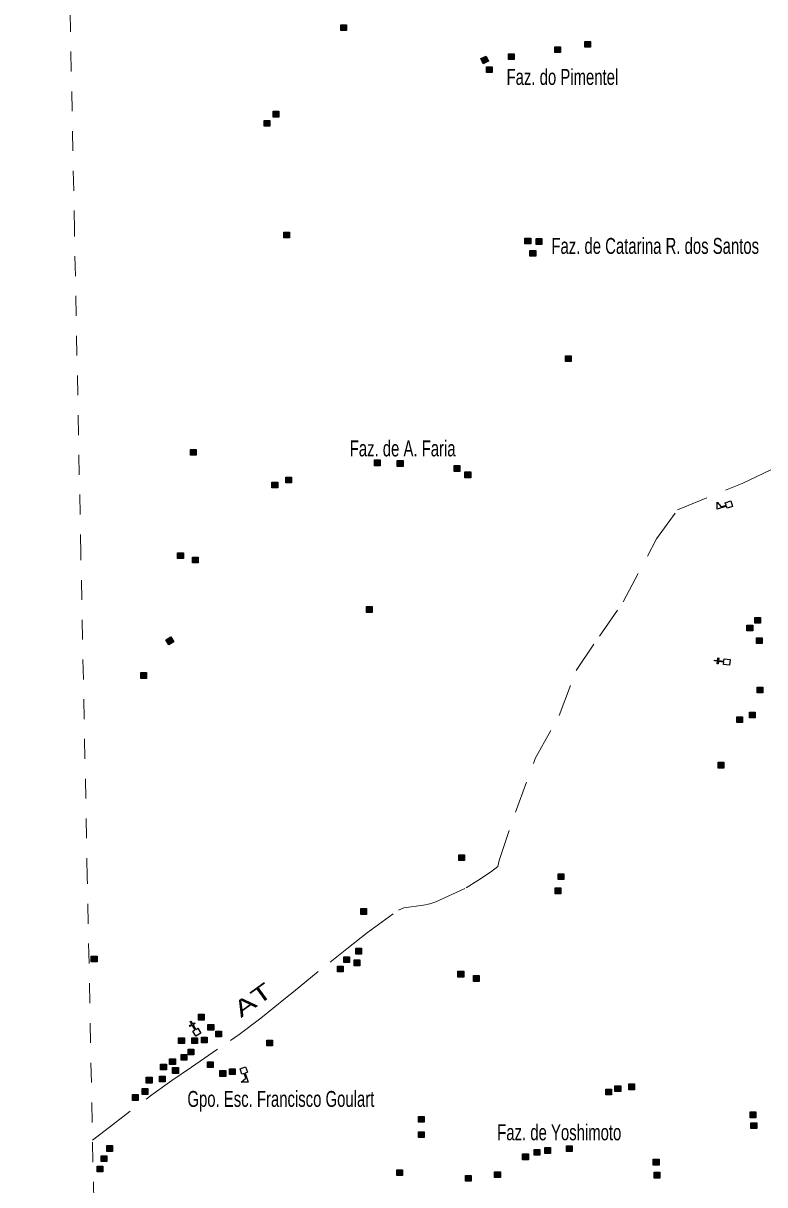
# Model space of a CAD drawing. Extents: x 220.8 to 246.7, y 7287.6 to 7315.8.
# Drawn here: x 220.75 to 224.49, y 7297.47 to 7303.31 of the extents above; entities that cross this region are included whole.
import ezdxf
from ezdxf.enums import TextEntityAlignment as Align

# ---------------------------------------------------------------- set-up
doc = ezdxf.new("R2010")
doc.units = 0
doc.header["$LTSCALE"] = 0.032
doc.linetypes.add('DOT_DASHED', pattern=[7.7, 5, -1.2, 0.3, -1.2])
doc.linetypes.add('SHORT_DASHED', pattern=[2.7, 1.5, -1.2])
for name, color, linetype, lineweight in [('2', 7, 'Continuous', 25), ('4', 7, 'Continuous', 25), ('56', 7, 'DOT_DASHED', 13), ('58', 7, 'SHORT_DASHED', 13), ('6', 7, 'Continuous', 25)]:
    doc.layers.add(name, color=color, linetype=linetype, lineweight=lineweight)
doc.layers.add('61', color=7, linetype='Continuous')

msp = doc.modelspace()

# ---------------------------------------------------------------- hatches: boundary and pattern name
at = {"layer": '2'}
for points in [[(222.3516, 7303.3033), (222.3806, 7303.3033), (222.3806, 7303.2743), (222.3516, 7303.2743)], [(223.4281, 7303.1937), (223.4571, 7303.1937), (223.4571, 7303.1647), (223.4281, 7303.1647)], [(223.5792, 7303.2201), (223.6082, 7303.2201), (223.6082, 7303.1911), (223.5792, 7303.1911)], [(223.0565, 7303.1339), (223.0827, 7303.1462), (223.095, 7303.12), (223.0688, 7303.1077)], [(223.1955, 7303.1577), (223.2245, 7303.1577), (223.2245, 7303.1287), (223.1955, 7303.1287)], [(223.0852, 7303.093), (223.1142, 7303.093), (223.1142, 7303.064), (223.0852, 7303.064)], [(222.0121, 7302.8685), (222.0411, 7302.8685), (222.0411, 7302.8395), (222.0121, 7302.8395)], [(221.9664, 7302.8227), (221.9954, 7302.8227), (221.9954, 7302.7937), (221.9664, 7302.7937)], [(222.0653, 7302.2606), (222.0943, 7302.2606), (222.0943, 7302.2316), (222.0653, 7302.2316)], [(223.2785, 7302.2307), (223.3075, 7302.2307), (223.3075, 7302.2017), (223.2785, 7302.2017)], [(223.3349, 7302.2276), (223.3639, 7302.2276), (223.3639, 7302.1986), (223.3349, 7302.1986)], [(223.3036, 7302.168), (223.3326, 7302.168), (223.3326, 7302.139), (223.3036, 7302.139)], [(223.4822, 7301.6383), (223.5112, 7301.6383), (223.5112, 7301.6093), (223.4822, 7301.6093)], [(221.5952, 7301.1667), (221.6242, 7301.1667), (221.6242, 7301.1377), (221.5952, 7301.1377)], [(222.5214, 7301.1139), (222.5504, 7301.1139), (222.5504, 7301.0849), (222.5214, 7301.0849)], [(222.636, 7301.1107), (222.665, 7301.1107), (222.665, 7301.0817), (222.636, 7301.0817)], [(222.9226, 7301.0853), (222.9516, 7301.0853), (222.9516, 7301.0563), (222.9226, 7301.0563)], [(222.0757, 7301.0279), (222.1047, 7301.0279), (222.1047, 7300.9989), (222.0757, 7300.9989)], [(222.9767, 7301.0534), (223.0057, 7301.0534), (223.0057, 7301.0244), (222.9767, 7301.0244)], [(222.0057, 7301.0025), (222.0347, 7301.0025), (222.0347, 7300.9735), (222.0057, 7300.9735)], [(221.5311, 7300.6473), (221.5601, 7300.6473), (221.5601, 7300.6183), (221.5311, 7300.6183)], [(221.6058, 7300.6246), (221.6348, 7300.6246), (221.6348, 7300.5956), (221.6058, 7300.5956)], [(222.4807, 7300.3757), (222.5097, 7300.3757), (222.5097, 7300.3467), (222.4807, 7300.3467)], [(224.3957, 7300.2821), (224.4247, 7300.2821), (224.4247, 7300.2531), (224.3957, 7300.2531)], [(224.4351, 7300.3215), (224.4641, 7300.3215), (224.4641, 7300.2925), (224.4351, 7300.2925)], [(221.4965, 7300.2236), (221.5112, 7300.1985), (221.4861, 7300.1839), (221.4715, 7300.2089)], [(224.443, 7300.219), (224.472, 7300.219), (224.472, 7300.19), (224.443, 7300.19)], [(221.3461, 7300.0436), (221.3751, 7300.0436), (221.3751, 7300.0146), (221.3461, 7300.0146)], [(224.447, 7299.9708), (224.476, 7299.9708), (224.476, 7299.9418), (224.447, 7299.9418)], [(224.3445, 7299.821), (224.3735, 7299.821), (224.3735, 7299.792), (224.3445, 7299.792)], [(224.4076, 7299.8447), (224.4366, 7299.8447), (224.4366, 7299.8157), (224.4076, 7299.8157)], [(224.2499, 7299.5925), (224.2789, 7299.5925), (224.2789, 7299.5635), (224.2499, 7299.5635)], [(222.9451, 7299.1271), (222.9741, 7299.1271), (222.9741, 7299.0981), (222.9451, 7299.0981)], [(223.446, 7299.0317), (223.475, 7299.0317), (223.475, 7299.0027), (223.446, 7299.0027)], [(223.4302, 7298.9602), (223.4592, 7298.9602), (223.4592, 7298.9312), (223.4302, 7298.9312)], [(222.4527, 7298.8562), (222.4817, 7298.8562), (222.4817, 7298.8272), (222.4527, 7298.8272)], [(222.428, 7298.6562), (222.457, 7298.6562), (222.457, 7298.6272), (222.428, 7298.6272)], [(221.0969, 7298.6175), (221.1259, 7298.6175), (221.1259, 7298.5885), (221.0969, 7298.5885)], [(222.3665, 7298.6131), (222.3955, 7298.6131), (222.3955, 7298.5841), (222.3665, 7298.5841)], [(222.4188, 7298.5977), (222.4478, 7298.5977), (222.4478, 7298.5687), (222.4188, 7298.5687)], [(222.3357, 7298.5669), (222.3647, 7298.5669), (222.3647, 7298.5379), (222.3357, 7298.5379)], [(222.9416, 7298.5405), (222.9706, 7298.5405), (222.9706, 7298.5115), (222.9416, 7298.5115)], [(223.0199, 7298.5189), (223.0489, 7298.5189), (223.0489, 7298.4899), (223.0199, 7298.4899)], [(221.6355, 7298.324), (221.6645, 7298.324), (221.6645, 7298.295), (221.6355, 7298.295)], [(221.6838, 7298.2727), (221.7128, 7298.2727), (221.7128, 7298.2437), (221.6838, 7298.2437)], [(221.7229, 7298.2395), (221.7519, 7298.2395), (221.7519, 7298.2105), (221.7229, 7298.2105)], [(221.536, 7298.2064), (221.565, 7298.2064), (221.565, 7298.1774), (221.536, 7298.1774)], [(221.6023, 7298.2064), (221.6313, 7298.2064), (221.6313, 7298.1774), (221.6023, 7298.1774)], [(221.6506, 7298.2094), (221.6796, 7298.2094), (221.6796, 7298.1804), (221.6506, 7298.1804)], [(221.9792, 7298.1943), (222.0082, 7298.1943), (222.0082, 7298.1653), (221.9792, 7298.1653)], [(221.5481, 7298.1219), (221.5771, 7298.1219), (221.5771, 7298.0929), (221.5481, 7298.0929)], [(221.5842, 7298.1491), (221.6132, 7298.1491), (221.6132, 7298.1201), (221.5842, 7298.1201)], [(221.4455, 7298.0737), (221.4745, 7298.0737), (221.4745, 7298.0447), (221.4455, 7298.0447)], [(221.4908, 7298.1008), (221.5198, 7298.1008), (221.5198, 7298.0718), (221.4908, 7298.0718)], [(221.5058, 7298.0556), (221.5348, 7298.0556), (221.5348, 7298.0266), (221.5058, 7298.0266)], [(221.6807, 7298.0857), (221.7097, 7298.0857), (221.7097, 7298.0567), (221.6807, 7298.0567)], [(221.7923, 7298.0496), (221.8213, 7298.0496), (221.8213, 7298.0206), (221.7923, 7298.0206)], [(221.3732, 7298.0073), (221.4022, 7298.0073), (221.4022, 7297.9783), (221.3732, 7297.9783)], [(221.4395, 7298.0134), (221.4685, 7298.0134), (221.4685, 7297.9844), (221.4395, 7297.9844)], [(221.7441, 7298.0405), (221.7731, 7298.0405), (221.7731, 7298.0115), (221.7441, 7298.0115)], [(221.3521, 7297.9501), (221.3811, 7297.9501), (221.3811, 7297.9211), (221.3521, 7297.9211)], [(223.6856, 7297.9475), (223.7146, 7297.9475), (223.7146, 7297.9185), (223.6856, 7297.9185)], [(223.7313, 7297.9649), (223.7603, 7297.9649), (223.7603, 7297.9359), (223.7313, 7297.9359)], [(223.8011, 7297.9736), (223.8301, 7297.9736), (223.8301, 7297.9446), (223.8011, 7297.9446)], [(221.3038, 7297.9199), (221.3328, 7297.9199), (221.3328, 7297.8909), (221.3038, 7297.8909)], [(224.4114, 7297.8328), (224.4404, 7297.8328), (224.4404, 7297.8038), (224.4114, 7297.8038)], [(222.7428, 7297.8098), (222.7718, 7297.8098), (222.7718, 7297.7808), (222.7428, 7297.7808)], [(224.4158, 7297.7782), (224.4448, 7297.7782), (224.4448, 7297.7492), (224.4158, 7297.7492)], [(222.7428, 7297.7332), (222.7718, 7297.7332), (222.7718, 7297.7042), (222.7428, 7297.7042)], [(221.1746, 7297.6632), (221.2036, 7297.6632), (221.2036, 7297.6342), (221.1746, 7297.6342)], [(223.3241, 7297.6437), (223.3531, 7297.6437), (223.3531, 7297.6147), (223.3241, 7297.6147)], [(223.3784, 7297.6533), (223.4074, 7297.6533), (223.4074, 7297.6243), (223.3784, 7297.6243)], [(223.487, 7297.6629), (223.516, 7297.6629), (223.516, 7297.6339), (223.487, 7297.6339)], [(221.1456, 7297.6117), (221.1746, 7297.6117), (221.1746, 7297.5827), (221.1456, 7297.5827)], [(223.2666, 7297.6214), (223.2956, 7297.6214), (223.2956, 7297.5924), (223.2666, 7297.5924)], [(223.9244, 7297.5947), (223.9534, 7297.5947), (223.9534, 7297.5657), (223.9244, 7297.5657)], [(221.1263, 7297.5603), (221.1553, 7297.5603), (221.1553, 7297.5313), (221.1263, 7297.5313)], [(222.6342, 7297.5415), (222.6632, 7297.5415), (222.6632, 7297.5125), (222.6342, 7297.5125)], [(223.1261, 7297.5319), (223.1551, 7297.5319), (223.1551, 7297.5029), (223.1261, 7297.5029)], [(223.9288, 7297.5292), (223.9578, 7297.5292), (223.9578, 7297.5002), (223.9288, 7297.5002)], [(222.9792, 7297.5127), (223.0082, 7297.5127), (223.0082, 7297.4837), (222.9792, 7297.4837)]]:
    msp.add_hatch(color=256, dxfattribs=at).paths.add_polyline_path(points)

# ---------------------------------------------------------------- linework, layer by layer
for points in [[(222.3516, 7303.3033), (222.3806, 7303.3033), (222.3806, 7303.2743), (222.3516, 7303.2743)], [(223.4281, 7303.1937), (223.4571, 7303.1937), (223.4571, 7303.1647), (223.4281, 7303.1647)], [(223.5792, 7303.2201), (223.6082, 7303.2201), (223.6082, 7303.1911), (223.5792, 7303.1911)], [(223.0565, 7303.1339), (223.0827, 7303.1462), (223.095, 7303.12), (223.0688, 7303.1077)], [(223.1955, 7303.1577), (223.2245, 7303.1577), (223.2245, 7303.1287), (223.1955, 7303.1287)], [(223.0852, 7303.093), (223.1142, 7303.093), (223.1142, 7303.064), (223.0852, 7303.064)], [(222.0121, 7302.8685), (222.0411, 7302.8685), (222.0411, 7302.8395), (222.0121, 7302.8395)], [(221.9664, 7302.8227), (221.9954, 7302.8227), (221.9954, 7302.7937), (221.9664, 7302.7937)], [(222.0653, 7302.2606), (222.0943, 7302.2606), (222.0943, 7302.2316), (222.0653, 7302.2316)], [(223.2785, 7302.2307), (223.3075, 7302.2307), (223.3075, 7302.2017), (223.2785, 7302.2017)], [(223.3349, 7302.2276), (223.3639, 7302.2276), (223.3639, 7302.1986), (223.3349, 7302.1986)], [(223.3036, 7302.168), (223.3326, 7302.168), (223.3326, 7302.139), (223.3036, 7302.139)], [(223.4822, 7301.6383), (223.5112, 7301.6383), (223.5112, 7301.6093), (223.4822, 7301.6093)], [(221.5952, 7301.1667), (221.6242, 7301.1667), (221.6242, 7301.1377), (221.5952, 7301.1377)], [(222.5214, 7301.1139), (222.5504, 7301.1139), (222.5504, 7301.0849), (222.5214, 7301.0849)], [(222.636, 7301.1107), (222.665, 7301.1107), (222.665, 7301.0817), (222.636, 7301.0817)], [(222.9226, 7301.0853), (222.9516, 7301.0853), (222.9516, 7301.0563), (222.9226, 7301.0563)], [(222.0757, 7301.0279), (222.1047, 7301.0279), (222.1047, 7300.9989), (222.0757, 7300.9989)], [(222.9767, 7301.0534), (223.0057, 7301.0534), (223.0057, 7301.0244), (222.9767, 7301.0244)], [(222.0057, 7301.0025), (222.0347, 7301.0025), (222.0347, 7300.9735), (222.0057, 7300.9735)], [(221.5311, 7300.6473), (221.5601, 7300.6473), (221.5601, 7300.6183), (221.5311, 7300.6183)], [(221.6058, 7300.6246), (221.6348, 7300.6246), (221.6348, 7300.5956), (221.6058, 7300.5956)], [(222.4807, 7300.3757), (222.5097, 7300.3757), (222.5097, 7300.3467), (222.4807, 7300.3467)], [(224.3957, 7300.2821), (224.4247, 7300.2821), (224.4247, 7300.2531), (224.3957, 7300.2531)], [(224.4351, 7300.3215), (224.4641, 7300.3215), (224.4641, 7300.2925), (224.4351, 7300.2925)], [(221.4965, 7300.2236), (221.5112, 7300.1985), (221.4861, 7300.1839), (221.4715, 7300.2089)], [(224.443, 7300.219), (224.472, 7300.219), (224.472, 7300.19), (224.443, 7300.19)], [(221.3461, 7300.0436), (221.3751, 7300.0436), (221.3751, 7300.0146), (221.3461, 7300.0146)], [(224.447, 7299.9708), (224.476, 7299.9708), (224.476, 7299.9418), (224.447, 7299.9418)], [(224.3445, 7299.821), (224.3735, 7299.821), (224.3735, 7299.792), (224.3445, 7299.792)], [(224.4076, 7299.8447), (224.4366, 7299.8447), (224.4366, 7299.8157), (224.4076, 7299.8157)], [(224.2499, 7299.5925), (224.2789, 7299.5925), (224.2789, 7299.5635), (224.2499, 7299.5635)], [(222.9451, 7299.1271), (222.9741, 7299.1271), (222.9741, 7299.0981), (222.9451, 7299.0981)], [(223.446, 7299.0317), (223.475, 7299.0317), (223.475, 7299.0027), (223.446, 7299.0027)], [(223.4302, 7298.9602), (223.4592, 7298.9602), (223.4592, 7298.9312), (223.4302, 7298.9312)], [(222.4527, 7298.8562), (222.4817, 7298.8562), (222.4817, 7298.8272), (222.4527, 7298.8272)], [(222.428, 7298.6562), (222.457, 7298.6562), (222.457, 7298.6272), (222.428, 7298.6272)], [(221.0969, 7298.6175), (221.1259, 7298.6175), (221.1259, 7298.5885), (221.0969, 7298.5885)], [(222.3665, 7298.6131), (222.3955, 7298.6131), (222.3955, 7298.5841), (222.3665, 7298.5841)], [(222.4188, 7298.5977), (222.4478, 7298.5977), (222.4478, 7298.5687), (222.4188, 7298.5687)], [(222.3357, 7298.5669), (222.3647, 7298.5669), (222.3647, 7298.5379), (222.3357, 7298.5379)], [(222.9416, 7298.5405), (222.9706, 7298.5405), (222.9706, 7298.5115), (222.9416, 7298.5115)], [(223.0199, 7298.5189), (223.0489, 7298.5189), (223.0489, 7298.4899), (223.0199, 7298.4899)], [(221.6355, 7298.324), (221.6645, 7298.324), (221.6645, 7298.295), (221.6355, 7298.295)], [(221.6838, 7298.2727), (221.7128, 7298.2727), (221.7128, 7298.2437), (221.6838, 7298.2437)], [(221.7229, 7298.2395), (221.7519, 7298.2395), (221.7519, 7298.2105), (221.7229, 7298.2105)], [(221.536, 7298.2064), (221.565, 7298.2064), (221.565, 7298.1774), (221.536, 7298.1774)], [(221.6023, 7298.2064), (221.6313, 7298.2064), (221.6313, 7298.1774), (221.6023, 7298.1774)], [(221.6506, 7298.2094), (221.6796, 7298.2094), (221.6796, 7298.1804), (221.6506, 7298.1804)], [(221.9792, 7298.1943), (222.0082, 7298.1943), (222.0082, 7298.1653), (221.9792, 7298.1653)], [(221.5481, 7298.1219), (221.5771, 7298.1219), (221.5771, 7298.0929), (221.5481, 7298.0929)], [(221.5842, 7298.1491), (221.6132, 7298.1491), (221.6132, 7298.1201), (221.5842, 7298.1201)], [(221.4455, 7298.0737), (221.4745, 7298.0737), (221.4745, 7298.0447), (221.4455, 7298.0447)], [(221.4908, 7298.1008), (221.5198, 7298.1008), (221.5198, 7298.0718), (221.4908, 7298.0718)], [(221.5058, 7298.0556), (221.5348, 7298.0556), (221.5348, 7298.0266), (221.5058, 7298.0266)], [(221.6807, 7298.0857), (221.7097, 7298.0857), (221.7097, 7298.0567), (221.6807, 7298.0567)], [(221.7923, 7298.0496), (221.8213, 7298.0496), (221.8213, 7298.0206), (221.7923, 7298.0206)], [(221.3732, 7298.0073), (221.4022, 7298.0073), (221.4022, 7297.9783), (221.3732, 7297.9783)], [(221.4395, 7298.0134), (221.4685, 7298.0134), (221.4685, 7297.9844), (221.4395, 7297.9844)], [(221.7441, 7298.0405), (221.7731, 7298.0405), (221.7731, 7298.0115), (221.7441, 7298.0115)], [(221.3521, 7297.9501), (221.3811, 7297.9501), (221.3811, 7297.9211), (221.3521, 7297.9211)], [(223.6856, 7297.9475), (223.7146, 7297.9475), (223.7146, 7297.9185), (223.6856, 7297.9185)], [(223.7313, 7297.9649), (223.7603, 7297.9649), (223.7603, 7297.9359), (223.7313, 7297.9359)], [(223.8011, 7297.9736), (223.8301, 7297.9736), (223.8301, 7297.9446), (223.8011, 7297.9446)], [(221.3038, 7297.9199), (221.3328, 7297.9199), (221.3328, 7297.8909), (221.3038, 7297.8909)], [(224.4114, 7297.8328), (224.4404, 7297.8328), (224.4404, 7297.8038), (224.4114, 7297.8038)], [(222.7428, 7297.8098), (222.7718, 7297.8098), (222.7718, 7297.7808), (222.7428, 7297.7808)], [(224.4158, 7297.7782), (224.4448, 7297.7782), (224.4448, 7297.7492), (224.4158, 7297.7492)], [(222.7428, 7297.7332), (222.7718, 7297.7332), (222.7718, 7297.7042), (222.7428, 7297.7042)], [(221.1746, 7297.6632), (221.2036, 7297.6632), (221.2036, 7297.6342), (221.1746, 7297.6342)], [(223.3241, 7297.6437), (223.3531, 7297.6437), (223.3531, 7297.6147), (223.3241, 7297.6147)], [(223.3784, 7297.6533), (223.4074, 7297.6533), (223.4074, 7297.6243), (223.3784, 7297.6243)], [(223.487, 7297.6629), (223.516, 7297.6629), (223.516, 7297.6339), (223.487, 7297.6339)], [(221.1456, 7297.6117), (221.1746, 7297.6117), (221.1746, 7297.5827), (221.1456, 7297.5827)], [(223.2666, 7297.6214), (223.2956, 7297.6214), (223.2956, 7297.5924), (223.2666, 7297.5924)], [(223.9244, 7297.5947), (223.9534, 7297.5947), (223.9534, 7297.5657), (223.9244, 7297.5657)], [(221.1263, 7297.5603), (221.1553, 7297.5603), (221.1553, 7297.5313), (221.1263, 7297.5313)], [(222.6342, 7297.5415), (222.6632, 7297.5415), (222.6632, 7297.5125), (222.6342, 7297.5125)], [(223.1261, 7297.5319), (223.1551, 7297.5319), (223.1551, 7297.5029), (223.1261, 7297.5029)], [(223.9288, 7297.5292), (223.9578, 7297.5292), (223.9578, 7297.5002), (223.9288, 7297.5002)], [(222.9792, 7297.5127), (223.0082, 7297.5127), (223.0082, 7297.4837), (222.9792, 7297.4837)]]:
    msp.add_lwpolyline(points, close=True, dxfattribs=at)
at = {"layer": '4'}
for points in [[(224.2919, 7300.8819), (224.2462, 7300.866), (224.246, 7300.9019), (224.2656, 7300.878), (224.2903, 7300.8866)], [(224.2903, 7300.8866), (224.2864, 7300.8981), (224.3137, 7300.9076), (224.3232, 7300.8802), (224.2959, 7300.8707), (224.2919, 7300.8819)], [(221.8661, 7298.0268), (221.8546, 7298.023), (221.8454, 7298.0505), (221.873, 7298.0597), (221.8821, 7298.0321), (221.8707, 7298.0284)], [(221.8707, 7298.0284), (221.886, 7297.9824), (221.8502, 7297.9827), (221.8743, 7298.002), (221.8661, 7298.0268)]]:
    msp.add_lwpolyline(points, dxfattribs=at)
at = {"layer": '56'}
msp.add_lwpolyline([(221.1029, 7297.6911), (221.1659, 7297.7392), (221.4019, 7297.9193), (221.5013, 7297.9903), (221.6003, 7298.0579), (221.7976, 7298.1926), (221.8414, 7298.2225), (221.95, 7298.3053), (222.0739, 7298.4051), (222.1143, 7298.4377), (222.298, 7298.5873), (222.3818, 7298.653), (222.4869, 7298.7356), (222.6418, 7298.8484), (222.6693, 7298.8602), (222.7677, 7298.8733), (222.8005, 7298.8799), (222.8307, 7298.8904), (222.9829, 7298.9612), (223.0409, 7298.998), (223.1049, 7299.0386), (223.1425, 7299.0675), (223.1483, 7299.0975), (223.2308, 7299.3419), (223.3305, 7299.6117), (223.4507, 7299.8286), (223.5358, 7300.0544), (223.6531, 7300.2273), (223.7733, 7300.4003), (223.9404, 7300.7169), (224.0459, 7300.8635), (224.3713, 7300.9955), (224.5296, 7301.0717)], dxfattribs=at)
at = {"layer": '58'}
msp.add_lwpolyline([(221.3035, 7287.6034), (221.271, 7289.2329), (221.2386, 7290.8624), (221.2062, 7292.4919), (221.1738, 7294.1214), (221.1414, 7295.7509), (221.109, 7297.3804), (221.0767, 7299.0099), (221.0443, 7300.6394), (221.0121, 7302.2689), (220.9798, 7303.8984), (220.9475, 7305.5279), (220.9153, 7307.1574), (220.883, 7308.7869), (220.8508, 7310.4164), (220.8187, 7312.0459), (220.7865, 7313.6754), (220.7543, 7315.3049)], dxfattribs=at)
at = {"layer": '6'}
for points in [[(224.2795, 7300.0968), (224.2526, 7300.0999), (224.2512, 7300.0879), (224.2463, 7300.0885), (224.2477, 7300.1005), (224.2314, 7300.1023), (224.2319, 7300.1071), (224.2482, 7300.1052), (224.2496, 7300.1173), (224.2545, 7300.1167), (224.2531, 7300.1047), (224.28, 7300.1016)], [(224.28, 7300.1016), (224.2814, 7300.1136), (224.3102, 7300.1103), (224.3069, 7300.0815), (224.2781, 7300.0848), (224.2795, 7300.0968)], [(221.6183, 7298.2458), (221.6044, 7298.269), (221.594, 7298.2628), (221.5915, 7298.267), (221.6019, 7298.2732), (221.5934, 7298.2873), (221.5976, 7298.2897), (221.606, 7298.2757), (221.6164, 7298.2819), (221.6189, 7298.2777), (221.6085, 7298.2715), (221.6225, 7298.2482)], [(221.6225, 7298.2482), (221.6328, 7298.2545), (221.6478, 7298.2296), (221.6229, 7298.2147), (221.608, 7298.2395), (221.6183, 7298.2458)]]:
    msp.add_lwpolyline(points, dxfattribs=at)

# ---------------------------------------------------------------- texts
at = {"layer": '61', "width": 0.7}
for s, p in [('Faz. do Pimentel', (223.1861, 7303.0013)), ('Faz. de Catarina R. dos Santos', (223.4116, 7302.1511)), ('Faz. de A. Faria', (222.3969, 7301.1319)), ('Gpo. Esc. Francisco Goulart', (221.5803, 7297.8583)), ('Faz. de Yoshimoto', (223.139, 7297.6901))]:
    msp.add_text(s, height=0.08, dxfattribs=at).set_placement(p)
at = {"layer": '61', "width": 1.5}
msp.add_text('AT', height=0.08, rotation=35.84, dxfattribs=at).set_placement((221.9328, 7298.3642), align=Align.CENTER)

doc.saveas('drawing.dxf')
